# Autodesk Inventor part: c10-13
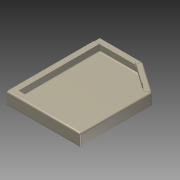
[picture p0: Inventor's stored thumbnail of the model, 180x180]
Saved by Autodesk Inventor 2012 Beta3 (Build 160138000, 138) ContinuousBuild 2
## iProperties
Created: 2011-01
Part Number: c10-13
Material: Steel, Mild
Document SubType Name: Sheet Metal
Designer: Beta-8540w
Density: 7.86 g/cm^3
Sheet Metal Rule: Steel - 16ga
Flat Pattern Width: 34.6788 cm
Flat Pattern Length: 40.6788 cm
Flat Pattern Area: 1410.69 cm^2
Sheet Metal Width: 346.788 mm
Sheet Metal Length: 406.788 mm
Sheet Metal Area: 141069.500 mm^2
Author: Beta-8540w
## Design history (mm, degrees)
node "Face1"
  sketch "Sketch1"
    geometry: L1 (0, 0)-(240, 0); L2 (240, 0)-(240, 300); L3 (240, 300)-(0, 300); L4 (0, 300)-(0, 0); L5 (140, 300)-(240, 229.979)
    constraints: 10 end point, 2 parallel, 2 point on line, 1 horizontal, 1 perpendicular
    dimensions: "d0" = 240 distance of L3.end L2.end; "d1" = 300 distance of L2.end L1.end; "d2" = 35 deg angle of L3 L5; "d3" = 100 distance from line of L2 L5.start
node "Flange1"
node "Flange2"
node "Flange3"
body "Solid1"
face "Plate1" dims "Thickness" = 1.524 (derived)
sketch "Sketch2"
  geometry: L1 (0, 40)-(-300, 40); L2 (-300, 40)-(-300, 0); 2 other entities
  constraints: 4 end point, 4 other
face "Plate2" dims "d5" = 1.524 (= BendReliefWidth), "d6" = 0.762 (= BendReliefDepth), "d7" = 3.048 (= MinimumRemnant), "d8" = 3.048 (= BendRadius), "d9" = 40, "d10" = 90 deg, "d11" = 3.048 (= BendRadius), "d12" = 6.096 (= CornerReliefSize), "d13" = 0.762 (= GapSize), "d14" = 3.048 (= JacobiRadiusSize), "SeamGap" = 0.01, "Thickness" = 1.524 (derived)
bend "Bend1" dims "d5" = 1.524 (= BendReliefWidth), "d6" = 0.762 (= BendReliefDepth), "d7" = 3.048 (= MinimumRemnant), "d8" = 3.048 (= BendRadius), "d9" = 40, "d10" = 90 deg, "d11" = 3.048 (= BendRadius), "SeamGap" = 0.01, "Thickness" = 1.524 (derived)
feature "Corner1" dims "d9" = 40, "d10" = 90 deg, "d12" = 6.096 (= CornerReliefSize), "d13" = 0.762 (= GapSize), "d14" = 3.048 (= JacobiRadiusSize)
sketch "Sketch3"
  geometry: L1 (0, 20)-(-235.874, 20); L2 (-235.874, 20)-(-235.874, 0); 2 other entities
  constraints: 4 end point, 4 other
face "Plate3" dims "d15" = 1.524 (= BendReliefWidth), "d16" = 0.762 (= BendReliefDepth), "d17" = 3.048 (= MinimumRemnant), "d18" = 3.048 (= BendRadius), "d19" = 20, "d20" = 90 deg, "d21" = 3.048 (= BendRadius), "d22" = 6.096 (= CornerReliefSize), "d23" = 0.762 (= GapSize), "d24" = 3.048 (= JacobiRadiusSize), "d26" = 10, "SeamGap" = 0.01, "Thickness" = 1.524 (derived)
bend "Bend2" dims "d15" = 1.524 (= BendReliefWidth), "d16" = 0.762 (= BendReliefDepth), "d17" = 3.048 (= MinimumRemnant), "d18" = 3.048 (= BendRadius), "d19" = 20, "d20" = 90 deg, "d21" = 3.048 (= BendRadius), "SeamGap" = 0.01, "Thickness" = 1.524 (derived)
feature "Corner2" dims "d19" = 20, "d20" = 90 deg, "d22" = 6.096 (= CornerReliefSize), "d23" = 0.762 (= GapSize), "d24" = 3.048 (= JacobiRadiusSize)
sketch "Sketch4"
  geometry: L1 (-94.531, 0)-(-10, 0); L2 (-10, 0)-(-10, 15); L3 (-10, 15)-(-94.531, 15); L4 (-94.531, 15)-(-94.531, 0)
  constraints: 8 end point
face "Plate4" dims "d27" = 1.524 (= BendReliefWidth), "d28" = 0.762 (= BendReliefDepth), "d29" = 3.048 (= MinimumRemnant), "d30" = 3.048 (= BendRadius), "d31" = 10, "d32" = 10, "d33" = 15, "d34" = 90 deg, "d35" = 3.048 (= BendRadius), "d36" = 6.096 (= CornerReliefSize), "d37" = 0.762 (= GapSize), "d38" = 3.048 (= JacobiRadiusSize), "SeamGap" = 0.01, "Thickness" = 1.524 (derived)
bend "Bend3" dims "d27" = 1.524 (= BendReliefWidth), "d28" = 0.762 (= BendReliefDepth), "d29" = 3.048 (= MinimumRemnant), "d30" = 3.048 (= BendRadius), "d33" = 15, "d34" = 90 deg, "d35" = 3.048 (= BendRadius), "SeamGap" = 0.01, "Thickness" = 1.524 (derived)
feature "Corner3" dims "d33" = 15, "d34" = 90 deg, "d36" = 6.096 (= CornerReliefSize), "d37" = 0.762 (= GapSize), "d38" = 3.048 (= JacobiRadiusSize)
feature "Definition1"
fillet "Fillet1" dims "d0" = 5
fillet "Fillet2" dims "d1" = 5
fillet "Fillet3" dims "d2" = 5
fillet "Fillet4" dims "d3" = 2
fillet "Fillet5" dims "d4" = 2
other parameters: "BendRadius" = 3.048 (= 2 x Thickness), "BendReliefWidth" = 1.524 (= Thickness), "BendReliefDepth" = 0.762 (= 0.5 x Thickness), "CornerReliefSize" = 6.096 (= 4 x Thickness), "MinimumRemnant" = 3.048 (= 2 x Thickness), "TransitionRadius" = 3.048 (= BendRadius), "JacobiRadiusSize" = 3.048 (= BendRadius), "GapSize" = 0.762 (= 0.5 x Thickness), "d4" = 3.048 (= BendRadius), "BendRadius" = 3.048, "BendReliefDepth" = 0.762, "BendReliefWidth" = 1.524, "CornerReliefSize" = 6.096, "GapSize" = 0.762, "JacobiRadiusSize" = 3.048, "MinimumRemnant" = 3.048, "Thickness" = 1.524, "TransitionRadius" = 3.048
